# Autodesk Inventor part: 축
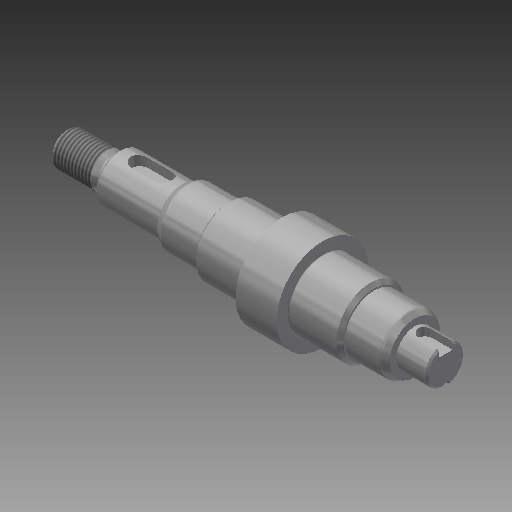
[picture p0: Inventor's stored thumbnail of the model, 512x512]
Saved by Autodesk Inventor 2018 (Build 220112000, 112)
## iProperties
Created: 2019-09
Part Number: 축
Material: 강철, 연강
Document SubType Name: Modeling
Designer: mduedu
Density: 7.86 g/cm^3
Mass: 210.278 g
Surface Area: 69.4769 cm^2
Volume: 26.7529 cm^3
Appearance: 강철
Author: mduedu
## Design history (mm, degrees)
sketch "스케치1"
  geometry: L1 (0, 0)-(15, 0); L2 (15, 0)-(15, 5); L3 (15, 5)-(0, 5); L4 (0, 5)-(0, 0); L5 (15, 0)-(34, 0); L6 (34, 0)-(34, 7); L7 (34, 7)-(15, 7); L8 (15, 7)-(15, 0); L9 (34, 0)-(47, 0); L10 (47, 0)-(47, 8.5); L11 (47, 8.5)-(34, 8.5); L12 (34, 8.5)-(34, 0); L13 (47, 0)-(63, 0); L14 (63, 0)-(63, 10); L15 (63, 10)-(47, 10); L16 (47, 10)-(47, 0); L17 (63, 0)-(75, 0); L18 (75, 0)-(75, 13.5); L19 (75, 13.5)-(63, 13.5); L20 (63, 13.5)-(63, 0); L21 (75, 0)-(90, 0); L22 (90, 0)-(90, 10); L23 (90, 10)-(75, 10); L24 (75, 10)-(75, 0); L25 (90, 0)-(102, 0); L26 (102, 0)-(102, 8.5); L27 (102, 8.5)-(90, 8.5); L28 (90, 8.5)-(90, 0); L29 (102, 0)-(111, 0); L30 (111, 0)-(111, 5.5); L31 (111, 5.5)-(102, 5.5); L32 (102, 5.5)-(102, 0)
  constraints: 64 end point, 16 parallel, 8 horizontal, 8 perpendicular
  dimensions: "d0" = 111 distance between parallel lines of L30 L4; "d2" = 15 distance of L2.end L3.end; "d3" = 19 distance of L6.end L7.end; "d4" = 12 distance of L18.end L19.end; "d5" = 15 distance of L22.end L23.end; "d6" = 12 distance of L26.end L27.end; "d7" = 9 distance of L30.end L31.end; "d8" = 16 distance of L14.end L15.end; "d9" = 10 diameter of L3 L1; "d10" = 14 diameter of L7 L5; "d11" = 17 diameter of L11 L9; "d12" = 20 diameter of L15 L13; "d13" = 27 diameter of L19 L17; "d14" = 20 diameter of L23 L21; "d15" = 17 diameter of L27 L25; "d16" = 11 diameter of L31 L29
revolve "회전1" sketch "스케치1" stored, may be unused: angle "d17" = 90 deg
sketch "스케치2"
  geometry: L1 (0, -5)-(0, 5) reference; L2 (0, 5)-(15, 5) reference; L3 (15, 5)-(15, 7) reference; L4 (15, 7)-(34, 7) reference; L5 (34, 7)-(34, 8.5) reference; L6 (34, 8.5)-(47, 8.5) reference; L7 (47, 8.5)-(47, 10) reference; L8 (47, 10)-(63, 10) reference; L9 (63, 10)-(63, 13.5) reference; L10 (63, 13.5)-(75, 13.5) reference; L11 (75, 13.5)-(75, 10) reference; L12 (75, 10)-(90, 10) reference; L13 (90, 10)-(90, 8.5) reference; L14 (90, 8.5)-(102, 8.5) reference; L15 (102, 8.5)-(102, 5.5) reference; L16 (102, 5.5)-(111, 5.5) reference; L17 (111, 5.5)-(111, -5.5) reference; L18 (111, -5.5)-(102, -5.5) reference; L19 (102, -5.5)-(102, -8.5) reference; L20 (102, -8.5)-(90, -8.5) reference; L21 (90, -8.5)-(90, -10) reference; L22 (90, -10)-(75, -10) reference; L23 (75, -10)-(75, -13.5) reference; L24 (75, -13.5)-(63, -13.5) reference; L25 (63, -13.5)-(63, -10) reference; L26 (63, -10)-(47, -10) reference; L27 (47, -10)-(47, -8.5) reference; L28 (47, -8.5)-(34, -8.5) reference; L29 (34, -8.5)-(34, -7) reference; L30 (34, -7)-(15, -7) reference; L31 (15, -7)-(15, -5) reference; L32 (15, -5)-(0, -5) reference; L33 (0, 0)-(111, 0); L34 (15, 5)-(12.014, 5); L35 (13.4, 4.2)-(15, 4.2); L36 (15, 4.2)-(15, 5); L37 (12.014, 5)-(13.4, 4.2)
  constraints: 10 end point, 1 horizontal, 1 midpoint, 1 parallel, 1 vertical
  dimensions: "d18" = 30 deg angle of L2 L37; "d19" = 8.4 diameter of L35 L33; "d21" = 2.986 distance from line of L34.end L36
revolve "회전2" sketch "스케치2" stored, may be unused: angle "d22" = 90 deg
fillet "모깎기1" dims "d23" = 0.6
feature "스레드1" dims "d24" = 10, "d25" = 0
chamfer "모따기1" distance "d26" = 1; stored, may be unused: second distance "d27" = 2, angle "d28" = 45 deg
chamfer "모따기2" distance "d29" = 1; stored, may be unused: second distance "d30" = 2, angle "d31" = 45 deg
chamfer "모따기3" distance "d32" = 1.819; stored, may be unused: second distance "d33" = 2, angle "d34" = 30 deg
fillet "모깎기2" dims "d35" = 2
chamfer "모따기4" distance "d36" = 1; stored, may be unused: second distance "d37" = 2, angle "d38" = 30 deg
fillet "모깎기3" dims "d39" = 0.3
chamfer "모따기5" distance "d40" = 1; stored, may be unused: second distance "d41" = 2, angle "d42" = 30 deg
chamfer "모따기6" distance "d43" = 1.819; stored, may be unused: second distance "d44" = 2, angle "d45" = 30 deg
chamfer "모따기7" distance "d46" = 0.5; stored, may be unused: second distance "d47" = 2, angle "d48" = 30 deg
fillet "모깎기4" dims "d49" = 2
node "작업 평면1"
sketch "스케치3" dims "d51" = 12
  geometry: L1 (3, -2.5)-(-4, -2.5); L2 (-4, -2.5)-(-4, 2.5); L3 (-4, 2.5)-(3, 2.5); L4 (3, 2.5)-(3, -2.5); L5 (-9.5, 7.45)-(-9.5, -7.45) reference; 3 further points
  constraints: 8 end point, 2 midpoint, 2 parallel, 2 vertical alignment, 1 horizontal, 1 horizontal alignment, 1 perpendicular, 4 other
  dimensions: "d50" = 3 dimension on L5; "d52" = 5 distance between parallel lines of L3 L1
extrude "돌출1" cut sketch "스케치3" distance "d53" = 3; taper "d54" = 0 deg
node "작업 평면3"
sketch "스케치4"
  geometry: L1 (-4.5, -5)-(-4.5, 5) reference; L2 (-4.5, -2)-(1.5, -2); L3 (1.5, -2)-(1.5, 2); L4 (1.5, 2)-(-4.5, 2); L5 (-4.5, 2)-(-4.5, -2); 3 further points
  constraints: 8 end point, 2 horizontal alignment, 2 midpoint, 2 parallel, 1 horizontal, 1 perpendicular, 1 point on line, 1 vertical alignment, 2 other
  dimensions: "d55" = 4 distance between parallel lines of L4 L2; "d57" = 8 dimension on L1
extrude "돌출2" cut sketch "스케치4" distance "d58" = 2.5; taper "d59" = 0 deg
sketch "스케치5"
  geometry: A1 r 5.5 centre (2, -3) between (0, 2.123) and (4, 2.123) reference; 2 further points
  constraints: 1 point on circle
hole "구멍1" sketch "스케치5" at (2, -8.5) diameter "d60" = 2.459; stored, may be unused: countersink angle "d64" = 90 deg, drill point angle "d66" = 118 deg; dims "d61" = 6, "d62" = 4, "d63" = 2, "d65" = 5
node "솔리드1"
node "절단 모서리 투영1"
